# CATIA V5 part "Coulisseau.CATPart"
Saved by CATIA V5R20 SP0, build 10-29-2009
Part number: Coulisseau
Bounding box of the stored display mesh (mm): x -18 to 15, y 141.828 to 166.087, z 64.357 to 74.995
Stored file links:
  D:\Dropbox\IAO_2011\MMS_GR2\IAO_2011_1495_fpittorino\fpittorino_IAO\IAO_2011_1495_fpittorino\Coulisseau.CATPart
  D:\Dropbox\IAO_2011\MMS_GR2\IAO_2011_1495_fpittorino\fpittorino_IAO\IAO_2011_1495_fpittorino\Product3.CATProduct
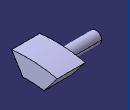
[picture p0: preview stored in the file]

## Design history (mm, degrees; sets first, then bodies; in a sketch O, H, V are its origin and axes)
External parameters (linked from other documents)
  External.L3 = 70 mm
Set1
  Plane1: linked copy from another document
  Point1: linked copy from another document
  Line1: linked copy from another document
  Point2: linked copy from another document
Body1 (main body)
  Sketch1 on Plane1, origin (0, 153.7432, 69.9), H (0, 0.0535, 0.9986), V (0, 0.9986, -0.0535)
    arc A1 centre (-70.0002, 0) radius 65 from (-5.2475, -5.6651) to (-5.2475, 5.6651) ccw
    point P1 (-70.0002, 0)
    reference projected point E1 (-70.0002, 0) from Point2
    arc A2 centre (-70.0002, 0) radius 75 from (4.0096, -12.147) to (4.0096, 12.147) ccw
    line L1 (4.0096, -12.147) -> (-5.2475, -5.6651)
    line L2 (4.0096, 12.147) -> (-5.2475, 5.6651)
    construction line L3 (-70.0002, 0) -> (0, 0)
    construction line L4 (-5.2475, -5.6651) -> (-70.0002, 0)
    axis line L5 (-5.2475, 5.6651) -> (-70.0002, 0)
    radius A1 = 65 {= External.L3 -5mm}
    radius A2 = 75 {= External.L3 +5mm}
    angle L5 L2 = 150
    angle L1 L4 = 150
    angle L2 H = 35
    angle L1 H = 35
    coincidence: P1 E1
    horizontal: L3 H
  Pad1: profile Sketch1, direction (1, 0, 0), length 15
  Sketch2 on Plane1, origin (0, 0, 0), H (0, 1, 0), V (0, 0, 1)
    circle A1 centre (153.7432, 69.9) radius 3
    point P1 (153.7432, 69.9)
    reference projected point E1 (153.7432, 69.9) from Point1
    radius A1 = 3
    coincidence: P1 E1
  Pad2: profile Sketch2, direction (-1, 0, 0), length 18
  Fillet1: radius 1, on edge [face of Pad2 from Sketch2.A1 | start face of Pad1]
  Point3: type OnCurve, Support edge [end face of Pad1 | face of Pad1 from Sketch1.A1], Length 5.005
